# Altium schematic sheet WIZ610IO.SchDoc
size A4; PageSetup: Record=PageOptions|CenterHorizontal=True|CenterVertical=True|PrintScale=0.97|XCorrection=1.00|YCorrection=1.00|PrintKind=1|BorderSize=5000000|LeftOffset=0|BottomOffset=0|Orientation=2|PaperLength=1000|PaperWidth=1000|Scale=100|PaperSource=7|PrintQuality=-3|MediaType=1|DitherType=10|PrintScaleMode=1|PaperKind=A4|PaperIndex=9
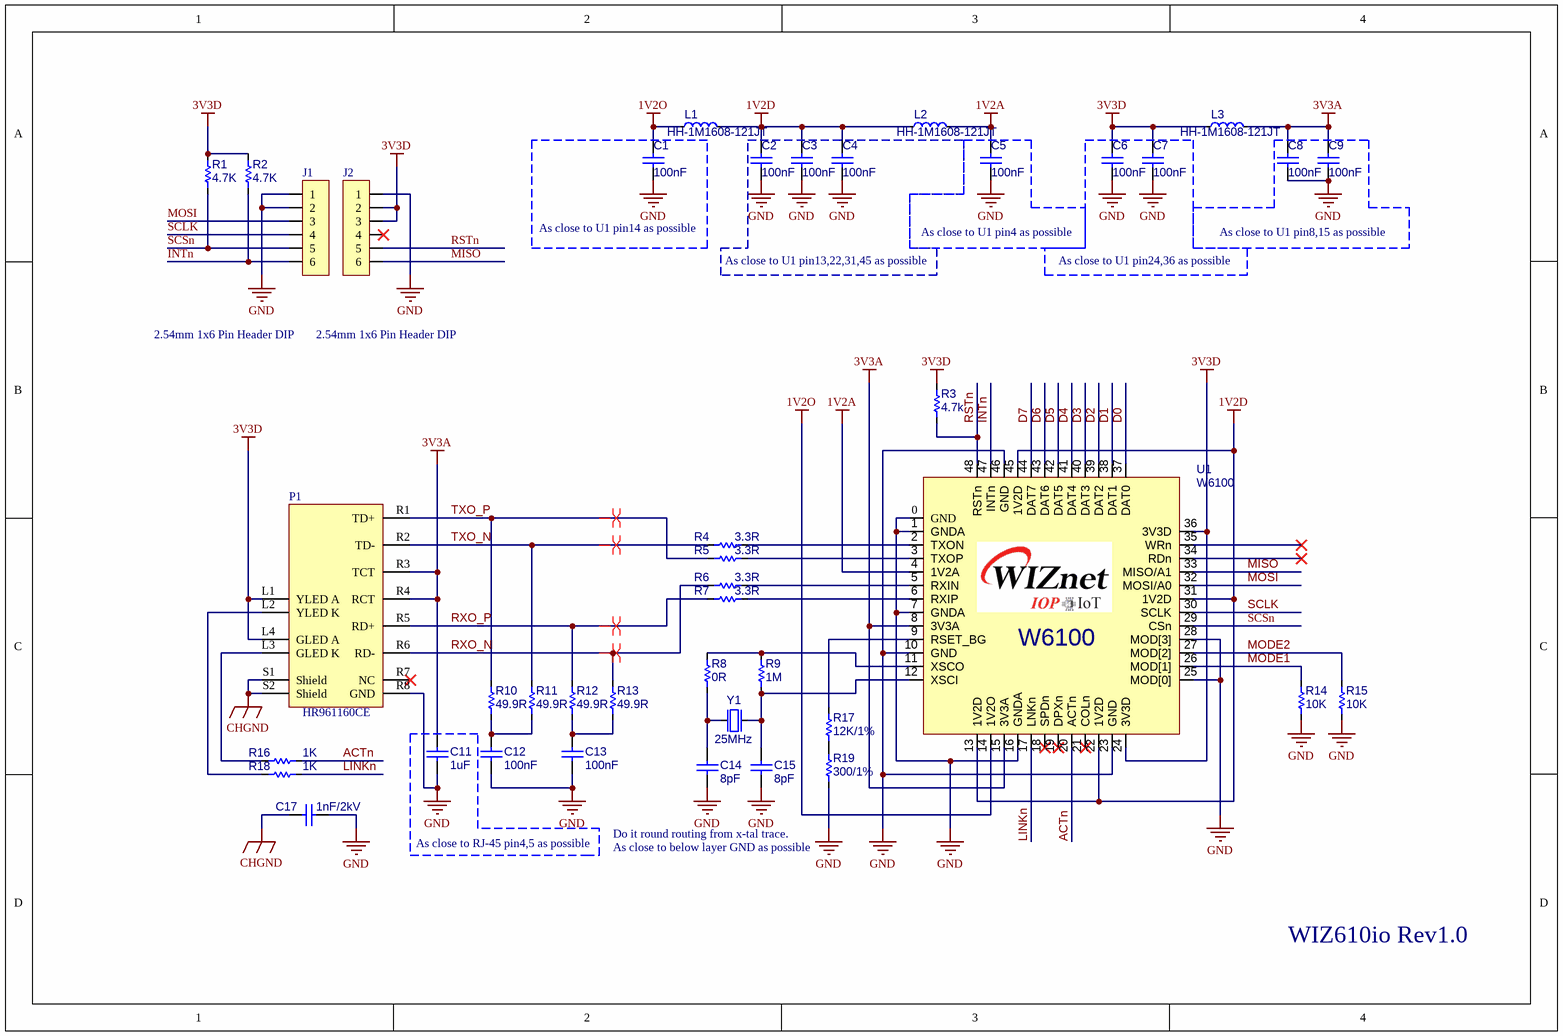
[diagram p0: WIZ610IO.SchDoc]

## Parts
C1  100nF  [0603-C]
C2  100nF  [0603-C]
C3  100nF  [0603-C]
C4  100nF  [0603-C]
C5  100nF  [0603-C]
C6  100nF  [0603-C]
C7  100nF  [0603-C]
C8  100nF  [0603-C]
C9  100nF  [0603-C]
C11  1uF  [0603-C]
C12  100nF  [0603-C]
C13  100nF  [0603-C]
C14  8pF  [0603-C]
C15  8pF  [0603-C]
C17  1nF/2kV  [CAP-1206]
J1  2.54mm 1x6 Pin Header DIP  [IDC-1X6]
J2  2.54mm 1x6 Pin Header DIP  [IDC-1X6]
L1  HH-1M1608-121JT  [0603-L]
L2  HH-1M1608-121JT  [0603-L]
L3  HH-1M1608-121JT  [0603-L]
P1  HR961160CE  [BS-R250210]
R1  4.7K  [0603-R]
R2  4.7K  [0603-R]
R3  4.7k  [0603-R]
R4  3.3R  [0603-R]
R5  3.3R  [0603-R]
R6  3.3R  [0603-R]
R7  3.3R  [0603-R]
R8  0R  [0603-R]
R9  1M  [0603-R]
R10  49.9R  [0603-R]
R11  49.9R  [0603-R]
R12  49.9R  [0603-R]
R13  49.9R  [0603-R]
R14  10K  [0603-R]
R15  10K  [0603-R]
R16  1K  [0603-R]
R17  12K/1%  [RES-0603]
R18  1K  [0603-R]
R19  300/1%  [RES-0603]
U1  W6100  [WIZNET W5100S QFN]
Y1  25MHz  [OSC-82J0626]

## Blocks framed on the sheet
As close to U1 pin14 as possible: C1
As close to U1 pin13,22,31,45 as possible: C2-C4
As close to U1 pin4 as possible: C5
As close to U1 pin24,36 as possible: C6 C7
As close to U1 pin8,15 as possible: C8 C9
As close to RJ-45 pin4,5 as possible: C11

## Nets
1V2A: C5.2 L2.2 U1.4(1V2A)
1V2D: C2.2 C3.2 C4.2 L1.2 L2.1 U1.13(1V2D) U1.22(1V2D) U1.31(1V2D) U1.45(1V2D)
1V2O: C1.2 L1.1 U1.14(1V2O)
3V3A: C8.2 C9.2 C11.2 L3.2 P1.R3(TCT) P1.R4(RCT) U1.8(3V3A) U1.15(3V3A)
3V3D: C6.2 C7.2 J2.2 J2.3 L3.1 P1.L1(YLED_A) P1.L4(GLED_A) R1.1 R2.1 R3.2 U1.24(3V3D) U1.36(3V3D)
CHGND: C17.1 P1.S1(Shield) P1.S2(Shield)
GND: C1.1 C2.1 C3.1 C4.1 C5.1 C6.1 C7.1 C8.1 C9.1 C11.1 C12.1 C13.1 C14.1 C15.1 C17.2 J1.1 J1.2 J2.1 P1.R8(GND) R14.1 R15.1 R19.1 U1.0(GND) U1.1(GNDA) U1.7(GNDA) U1.10(GND) U1.16(GNDA) U1.23(GND) U1.25(MOD[0]) U1.28(MOD[3]) U1.46(GND) Y1.2(GND) Y1.4(GND)
ACTn: R16.1 U1.20(ACTn)
D0: U1.37(DAT0)
D1: U1.38(DAT1)
D2: U1.39(DAT2)
D3: U1.40(DAT3)
D4: U1.41(DAT4)
D5: U1.42(DAT5)
D6: U1.43(DAT6)
D7: U1.44(DAT7)
INTn: J1.6 R2.2 U1.47(INTn)
LINKn: R18.1 U1.17(LNKn)
MISO: J2.6 U1.33(MISO/A1)
MODE1: R14.2 U1.26(MOD[1])
MODE2: R15.2 U1.27(MOD[2])
MOSI: J1.3 U1.32(MOSI/A0)
RSTn: J2.5 R3.1 U1.48(RSTn)
RXO_N: P1.R6(RD-) R6.2 R13.2
RXO_P: P1.R5(RD+) R7.2 R12.2
SCLK: J1.4 U1.30(SCLK)
SCSn: J1.5 R1.2 U1.29(CSn)
TXO_N: P1.R2(TD-) R4.2 R11.2
TXO_P: P1.R1(TD+) R5.2 R10.2
NetC12_2: C12.2 R10.1 R11.1
NetC13_2: C13.2 R12.1 R13.1
NetC14_2: C14.2 R8.1 Y1.1(inp)
NetC15_2: C15.2 R9.1 U1.12(XSCI) Y1.3(out)
NetP1_L2: P1.L2(YLED_K) R18.2
NetP1_L3: P1.L3(GLED_K) R16.2
NetR4_1: R4.1 U1.2(TXON)
NetR5_1: R5.1 U1.3(TXOP)
NetR6_1: R6.1 U1.5(RXIN)
NetR7_1: R7.1 U1.6(RXIP)
NetR8_2: R8.2 R9.2 U1.11(XSCO)
NetR17_1: R17.1 R19.2
NetR17_2: R17.2 U1.9(RSET_BG)

Not connected (* = marked no-connect by the designer): J2 4*; P1 R7(NC)*; U1 18(SPDn)* 19(DPXn)* 21(COLn)* 34(RDn)* 35(WRn)*

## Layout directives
differential pair: RXO_N, RXO_P, TXO_N, TXO_P

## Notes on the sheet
- Do it round routing from x-tal trace.
- As close to below layer GND as possible
- WIZ610io Rev1.0

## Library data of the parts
C1-C9 C11-C15 = CAP-0603: Ceramic CAP 0603(1608)
C17 = CAP-1808: Ceramic CAP 1808(4520)
L1-L3 = IND-0603: Inductor 0603(1608)
P1 = BS-R250210
R1-R19 = RES-0603: RES0603
U1 = W6100: WIZnet Hardwired TCP/IP Chip
Y1 = OSC-82J0626-25MHz: X-tal 25MHz,3.2x2.5 SMD, CL=18pF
